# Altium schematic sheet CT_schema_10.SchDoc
size 226 x 144 mm
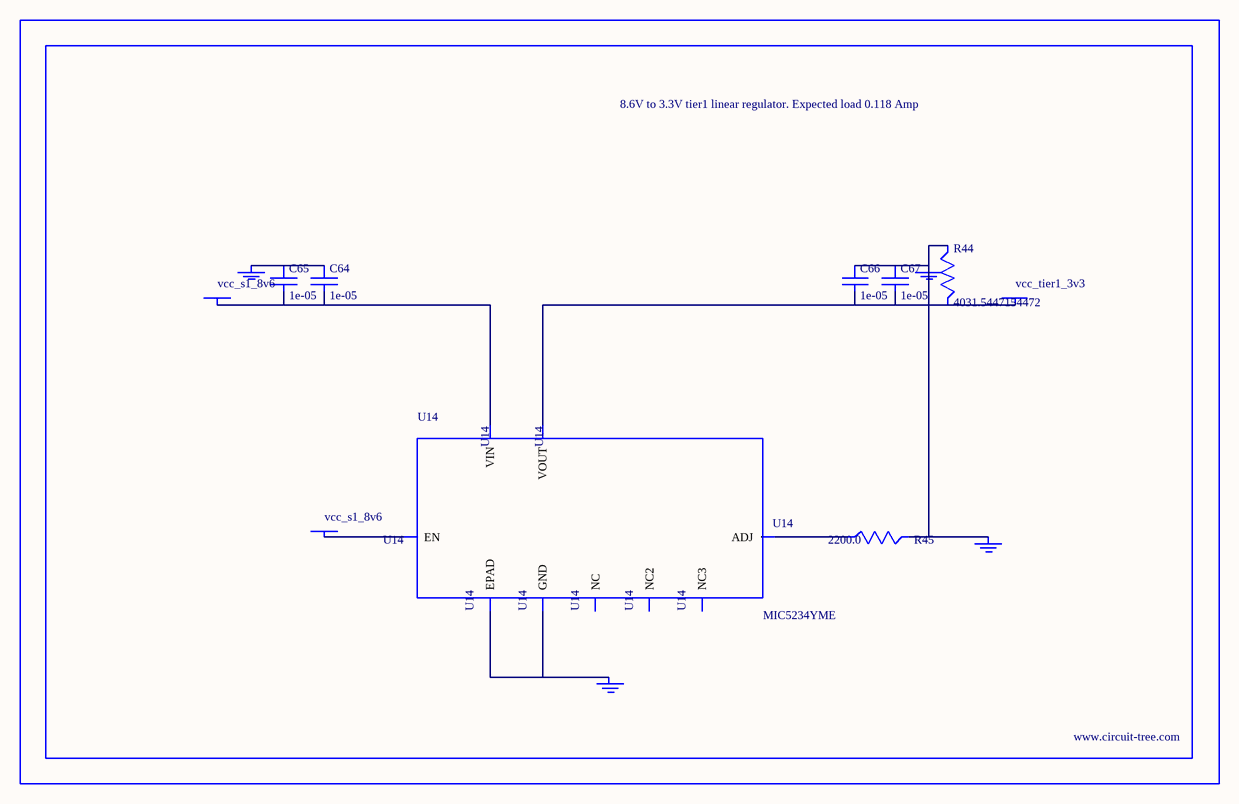
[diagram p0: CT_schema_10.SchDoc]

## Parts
BORDER9  (no value)
C64  1e-05  [C1210]
C65  1e-05  [C1210]
C66  1e-05  [C1210]
C67  1e-05  [C1210]
GND_INSTANCE_9_0  (no value)
GND_INSTANCE_9_1  (no value)
GND_INSTANCE_9_2  (no value)
GND_INSTANCE_9_3  (no value)
POWER_INSTANCE_9_0  vcc_tier1_3v3
POWER_INSTANCE_9_1  vcc_s1_8v6
POWER_INSTANCE_9_2  vcc_s1_8v6
R44  4031.5447154472  [R0603]
R45  2200.0  [R0603]
U14  MIC5234YME  [SOIC-8_EP]

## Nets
NetC64_1: C64.1 C65.1 GND_INSTANCE_9_3.0(GND)
NetC64_2: C64.2 C65.2 POWER_INSTANCE_9_2.0(PWR) U14.8(VIN)
NetC66_1: C66.1 C67.1 GND_INSTANCE_9_0.0(GND) GND_INSTANCE_9_1.0(GND) R44.1 R45.2
NetC66_2: C66.2 C67.2 POWER_INSTANCE_9_0.0(PWR) R44.2 U14.1(VOUT)
NetGND_INSTANCE_9_2_0: GND_INSTANCE_9_2.0(GND) U14.7(GND) U14.EPAD
NetPOWER_INSTANCE_9_1_0: POWER_INSTANCE_9_1.0(PWR) U14.5(EN)
NetR45_1: R45.1 U14.4(ADJ)

Not connected (* = marked no-connect by the designer): U14 2(NC) 3(NC2) 6(NC3)

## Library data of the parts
BORDER9 = BORDER_PAGE9
C64-C67 = C1210C106K5PACTU
GND_INSTANCE_9_0-GND_INSTANCE_9_3 = GND
POWER_INSTANCE_9_0-POWER_INSTANCE_9_2 = PWR
R44 = R44
R45 = RC0603JR-072K2L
